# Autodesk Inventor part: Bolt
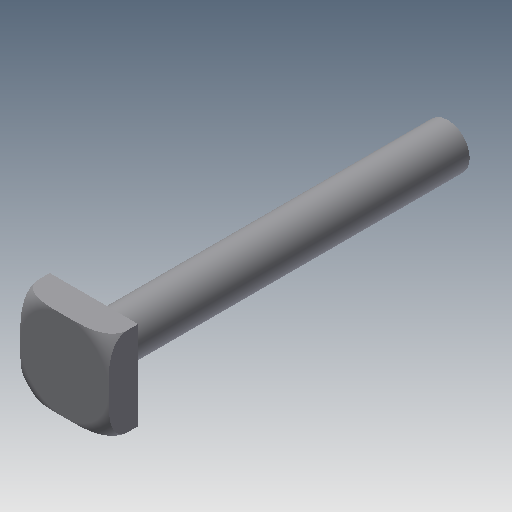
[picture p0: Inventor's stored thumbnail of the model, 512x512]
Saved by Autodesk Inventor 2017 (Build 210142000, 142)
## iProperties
Created: 2009-04
Part Number: Bolt
Document SubType Name: Modeling
Designer: Sham
Density: 1 g/cm^3
Material: Generic
Appearance: Default
Author: Sham
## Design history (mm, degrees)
sketch "Sketch1"
  geometry: L1 (-12, 12)-(12, 12); L2 (12, 12)-(12, -12); L3 (12, -12)-(-12, -12); L4 (-12, -12)-(-12, 12); 1 further point
  constraints: 8 end point, 2 parallel, 2 perpendicular, 1 horizontal, 1 other
  dimensions: "d0" = 24 distance of L1.start L1.end; "d1" = 12 distance from line of L2 point (0, 0); "d2" = 12 distance from line of L1 point (0, 0)
extrude "Extrusion1" new body sketch "Sketch1" distance "d3" = 8; taper "d4" = 0 deg
sketch "Sketch2"
  geometry: C1 r 6 at (0, 0)
  constraints: 1 centre point
  dimensions: "d5" = 12 diameter of C1
extrude "Extrusion2" join sketch "Sketch2" distance "d6" = 96; taper "d7" = 0 deg
workpoint "Work Point1"
workplane "Work Plane1"
sketch "Sketch3"
  geometry: L1 (33.941, 5)-(33.941, 6); L2 (28.941, 0)-(28.405, 0); L3 (16.971, 125.007)-(16.971, -22.043) reference; A1 r 5 centre (28.941, 5) between (28.941, 0) and (33.941, 5); 1 further point
  constraints: 4 end point, 2 point on circle, 2 point on line, 2 tangent, 1 centre point, 1 perpendicular
  dimensions: "d10" = 5 radius of A1
revolve "Revolution1" sketch "Sketch3" stored, may be unused: angle "d12" = 90 deg
body "Solid1"
other parameters: "d11" = 90 deg
